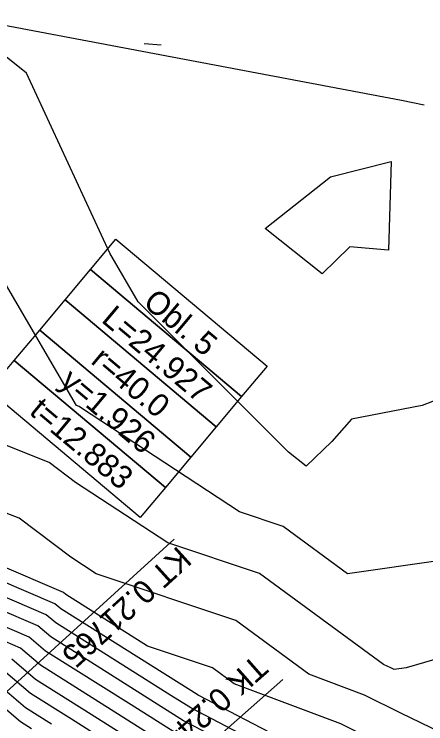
# Model space of a CAD drawing. Extents: x -549394 to -546608, y -1037055 to -1033629.
# Drawn here: x -546942 to -546879.5, y -1035904.5 to -1035796.8 of the extents above; entities that cross this region are included whole.
import ezdxf

# ---------------------------------------------------------------- set-up
doc = ezdxf.new("R2010")
doc.units = 0
for name, color, linetype in [('hlavni_vrst', 7, 'Continuous'), ('hrana_L', 7, 'Continuous'), ('norm_vrst', 7, 'Continuous'), ('x_popis_oblouky_C31', 7, 'Continuous')]:
    doc.layers.add(name, color=color, linetype=linetype)

msp = doc.modelspace()

# ---------------------------------------------------------------- linework, layer by layer
at = {"layer": 'hlavni_vrst'}
for p, q in [((-546932.55, -1035856.18), (-546943.33, -1035837.71)), ((-546932.17, -1035856.33), (-546932.55, -1035856.18)), ((-546931.94, -1035856.5), (-546932.17, -1035856.33)), ((-546907.78, -1035872.32), (-546931.94, -1035856.5)), ((-546901.13, -1035874.53), (-546907.78, -1035872.32)), ((-546891.39, -1035881.71), (-546901.13, -1035874.53)), ((-546874.66, -1035879.32), (-546891.39, -1035881.71)), ((-546937.14, -1035887.96), (-546945.36, -1035884.43)), ((-546935.72, -1035889.17), (-546937.14, -1035887.96)), ((-546918.21, -1035900.19), (-546935.72, -1035889.17)), ((-546939.54, -1035899.91), (-546943.67, -1035896.39)), ((-546933.34, -1035903.81), (-546939.54, -1035899.91)), ((-546915.18, -1035902.09), (-546918.21, -1035900.19)), ((-546898.67, -1035910.66), (-546915.18, -1035902.09)), ((-546920.66, -1035911.78), (-546933.34, -1035903.81))]:
    msp.add_line(p, q, dxfattribs=at)
at = {"layer": 'hrana_L'}
for p, q in [((-546952.42, -1035796.77), (-546883.17, -1035809.84)), ((-546883.17, -1035809.84), (-546879.7, -1035810.51))]:
    msp.add_line(p, q, dxfattribs=at)
at = {"layer": 'norm_vrst'}
for p, q in [((-546940.13, -1035805.7), (-546948.22, -1035799.39)), ((-546922.27, -1035801.2), (-546919.68, -1035801.42)), ((-546927.47, -1035833.03), (-546940.13, -1035805.7)), ((-546893.97, -1035821.46), (-546884.76, -1035819.12)), ((-546884.76, -1035819.12), (-546885.16, -1035832.61)), ((-546903.88, -1035829.28), (-546893.97, -1035821.46)), ((-546895.24, -1035836.17), (-546903.88, -1035829.28)), ((-546891.03, -1035832.09), (-546895.24, -1035836.17)), ((-546885.16, -1035832.61), (-546891.03, -1035832.09)), ((-546923.17, -1035840.45), (-546927.47, -1035833.03)), ((-546900.34, -1035863.25), (-546923.17, -1035840.45)), ((-546875.48, -1035854.38), (-546880.01, -1035856.19)), ((-546880.01, -1035856.19), (-546890.76, -1035858.26)), ((-546890.76, -1035858.26), (-546893.78, -1035861.66)), ((-546893.78, -1035861.66), (-546897.64, -1035865.4)), ((-546936.73, -1035864.81), (-546943.47, -1035862.17)), ((-546897.64, -1035865.4), (-546900.34, -1035863.25)), ((-546932.69, -1035867.86), (-546936.73, -1035864.81)), ((-546941.29, -1035873.29), (-546954.38, -1035868.17)), ((-546918.68, -1035877.03), (-546932.69, -1035867.86)), ((-546933.44, -1035879.22), (-546941.29, -1035873.29)), ((-546904.73, -1035881.68), (-546918.68, -1035877.03)), ((-546929.58, -1035881.75), (-546933.44, -1035879.22)), ((-546934.53, -1035884.59), (-546944.78, -1035880.18)), ((-546935.84, -1035886.27), (-546945.07, -1035882.31)), ((-546908.32, -1035888.83), (-546929.58, -1035881.75)), ((-546885.93, -1035895.52), (-546904.73, -1035881.68)), ((-546934.19, -1035884.87), (-546934.53, -1035884.59)), ((-546921.76, -1035892.7), (-546934.19, -1035884.87)), ((-546938.45, -1035889.64), (-546945.64, -1035886.55)), ((-546934.96, -1035887.02), (-546935.84, -1035886.27)), ((-546915.18, -1035899.46), (-546934.96, -1035887.02)), ((-546939.75, -1035891.33), (-546945.93, -1035888.68)), ((-546897.26, -1035896.97), (-546908.32, -1035888.83)), ((-546936.48, -1035891.32), (-546938.45, -1035889.64)), ((-546859.11, -1035889.31), (-546882.46, -1035895.99)), ((-546941.06, -1035893.02), (-546946.22, -1035890.8)), ((-546937.25, -1035893.47), (-546939.75, -1035891.33)), ((-546921.24, -1035900.91), (-546936.48, -1035891.32)), ((-546938.01, -1035895.62), (-546941.06, -1035893.02)), ((-546911.91, -1035895.98), (-546921.76, -1035892.7)), ((-546924.26, -1035901.64), (-546937.25, -1035893.47)), ((-546938.77, -1035897.76), (-546942.37, -1035894.7)), ((-546927.29, -1035902.36), (-546938.01, -1035895.62)), ((-546908.59, -1035898.43), (-546911.91, -1035895.98)), ((-546885.23, -1035895.78), (-546885.93, -1035895.52)), ((-546884.77, -1035896.01), (-546885.23, -1035895.78)), ((-546884.27, -1035896.25), (-546884.77, -1035896.01)), ((-546882.46, -1035895.99), (-546884.27, -1035896.25)), ((-546888.81, -1035900.14), (-546897.26, -1035896.97)), ((-546940.3, -1035902.06), (-546944.98, -1035898.08)), ((-546930.31, -1035903.09), (-546938.77, -1035897.76)), ((-546892.38, -1035904.5), (-546908.59, -1035898.43)), ((-546941.06, -1035904.21), (-546946.29, -1035899.76)), ((-546914.08, -1035900.15), (-546915.18, -1035899.46)), ((-546900.84, -1035907.02), (-546914.08, -1035900.15)), ((-546883.25, -1035902.9), (-546888.81, -1035900.14)), ((-546917.37, -1035905.97), (-546924.26, -1035901.64)), ((-546916.28, -1035904.03), (-546921.24, -1035900.91)), ((-546936.37, -1035904.54), (-546940.3, -1035902.06)), ((-546918.47, -1035907.91), (-546927.29, -1035902.36)), ((-546877.17, -1035905.8), (-546883.25, -1035902.9)), ((-546919.56, -1035909.84), (-546930.31, -1035903.09)), ((-546901.17, -1035911.87), (-546916.28, -1035904.03)), ((-546939.39, -1035905.26), (-546941.06, -1035904.21)), ((-546881.73, -1035909.8), (-546892.38, -1035904.5))]:
    msp.add_line(p, q, dxfattribs=at)
at = {"layer": 'x_popis_oblouky_C31'}
for points in [[(-546926.58, -1035830.94), (-546903.6, -1035850.22), (-546907.46, -1035854.82), (-546930.44, -1035835.53)], [(-546930.44, -1035835.53), (-546907.46, -1035854.82), (-546911.32, -1035859.42), (-546934.3, -1035840.13)], [(-546934.3, -1035840.13), (-546911.32, -1035859.42), (-546915.18, -1035864.01), (-546938.15, -1035844.72)], [(-546938.15, -1035844.72), (-546915.18, -1035864.01), (-546919.04, -1035868.61), (-546942.01, -1035849.32)], [(-546942.01, -1035849.32), (-546919.04, -1035868.61), (-546922.89, -1035873.2), (-546945.87, -1035853.91)]]:
    msp.add_lwpolyline(points, close=True, dxfattribs=at)
for points in [[(-546917.71, -1035876.48), (-546948.35, -1035904.28)], [(-546901.18, -1035897.79), (-546932.22, -1035925.15)]]:
    msp.add_lwpolyline(points, dxfattribs=at)

# ---------------------------------------------------------------- texts
for s, rotation, p in [('Obl. 5', 320.0082, (-546922.62, -1035840.86)), ('L=24.927', 320.0082, (-546928.94, -1035843.39)), ('r=40.0', 320.0082, (-546930.54, -1035849.65)), ('y=1.926', 320.0082, (-546935.28, -1035852.94)), ('t=12.883', 320.0082, (-546939.9, -1035857.35)), ('KT 0.21765', 222.2196, (-546917.14, -1035877.39)), ('TK 0.24402', 221.3899, (-546905.49, -1035893.86))]:
    msp.add_text(s, height=3.5, rotation=rotation, dxfattribs=at).set_placement(p)

doc.saveas('drawing.dxf')
